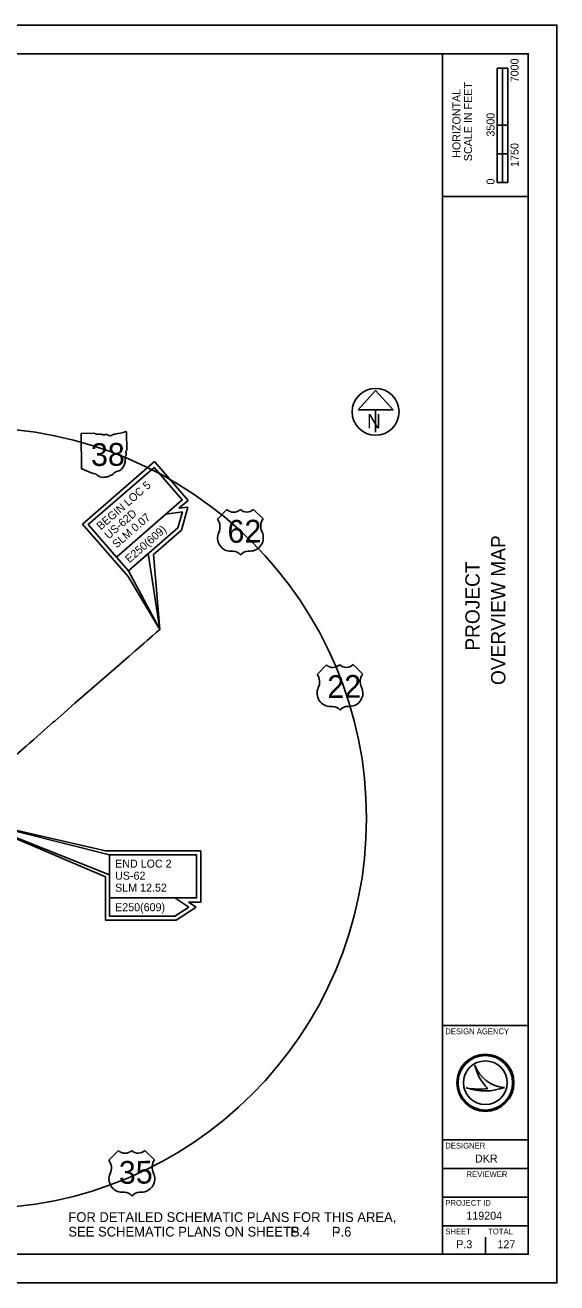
# Model space of a CAD drawing. Extents: x 86259 to 205259, y 423331 to 500331.
# Drawn here: x 172720 to 205259, y 423331 to 500331 of the extents above; entities that cross this region are included whole.
import ezdxf

# ---------------------------------------------------------------- set-up
doc = ezdxf.new("R2010")
doc.units = 0
for name, color, linetype in [('Default', 7, 'Continuous'), ('GM_X_County_Subdivision', 7, 'Continuous'), ('PM_P_Cells', 7, 'Continuous'), ('SC_Scratch1', 7, 'Continuous'), ('SH_Border', 7, 'Continuous'), ('SH_Cut_Line', 7, 'Continuous'), ('SH_Data', 7, 'Continuous'), ('SH_Text', 7, 'Continuous'), ('SN_P_Signs', 7, 'Continuous'), ('XS_P_Annotation', 7, 'Continuous')]:
    doc.layers.add(name, color=color, linetype=linetype)

msp = doc.modelspace()

# ---------------------------------------------------------------- linework, layer by layer
at = {"layer": 'GM_X_County_Subdivision'}
msp.add_circle((194167, 476659), 1435, dxfattribs=at)
at = {"layer": 'PM_P_Cells'}
for points in [[(180957, 463326), (180739, 463138), (180515, 462947), (180182, 462655), (180008, 462503), (179441, 462008), (179088, 461702), (177988, 460749), (177695, 460495), (177082, 459964), (176952, 459851), (175768, 458815), (175103, 458232), (174548, 457746), (174416, 457630)], [(174416, 457630), (173884, 457161), (173467, 456791), (173222, 456574), (172987, 456373), (172774, 456190), (172520, 455957), (172483, 455922), (172034, 455537), (171782, 455312), (171481, 455055)]]:
    msp.add_lwpolyline(points, dxfattribs=at)
at = {"layer": 'SC_Scratch1'}
for p, q in [((180630, 473610), (176228, 469788)), ((182689, 471239), (180630, 473610)), ((182130, 470754), (182689, 471239)), ((182682, 470828), (182130, 470754)), ((182284, 469414), (182682, 470828)), ((176228, 469788), (179016, 466577)), ((180570, 467926), (182284, 469414)), ((180957, 463326), (180570, 467926)), ((179016, 466577), (180957, 463326)), ((169524, 451634), (177634, 449784)), ((177634, 448192), (169524, 451634)), ((177634, 449784), (183464, 449784)), ((183464, 449784), (183464, 446644)), ((177634, 445531), (177634, 448192)), ((183464, 446644), (182724, 446644)), ((182724, 446644), (183190, 446338)), ((183190, 446338), (181962, 445531)), ((181962, 445531), (177634, 445531))]:
    msp.add_line(p, q, dxfattribs=at)
at = {"layer": 'SH_Border'}
for p, q in [((198259, 425081), (198259, 498581)), ((198259, 489831), (203509, 489831)), ((198259, 439081), (203509, 439081)), ((198259, 432081), (203509, 432081)), ((198259, 430331), (203509, 430331)), ((198259, 428581), (203509, 428581)), ((198259, 426831), (203509, 426831))]:
    msp.add_line(p, q, dxfattribs=at)
msp.add_lwpolyline([(91509, 498581), (203509, 498581), (203509, 425081), (91509, 425081)], close=True, dxfattribs=at)
msp.add_circle((169707, 451775), 23903, dxfattribs=at)
at = {"layer": 'SH_Cut_Line'}
msp.add_lwpolyline([(86259, 423331), (205259, 423331), (205259, 500331), (86259, 500331)], close=True, dxfattribs=at)
at = {"layer": 'SH_Data'}
for p, q in [((201607, 490706), (201607, 497706)), ((202263, 497706), (201607, 497706)), ((201607, 494206), (201607, 497706)), ((201607, 497706), (201934, 497706)), ((201934, 497706), (201937, 497706)), ((201937, 497706), (201937, 494206)), ((202263, 497706), (202263, 490706)), ((201937, 494206), (201607, 494206)), ((202260, 494206), (201934, 494206)), ((201934, 494206), (201934, 492456)), ((202260, 492456), (202260, 494206)), ((201934, 492456), (201607, 492456)), ((201607, 492456), (201607, 490706)), ((201934, 490706), (201934, 492456)), ((201934, 492456), (202260, 492456)), ((202263, 490706), (201607, 490706)), ((201607, 490706), (201934, 490706)), ((182339, 470530), (181334, 470394)), ((182339, 470530), (182064, 469554)), ((178311, 467770), (181334, 470394)), ((179040, 466930), (182064, 469554)), ((178311, 467770), (179040, 466930)), ((177884, 446894), (177884, 445781)), ((182735, 446338), (181888, 446894)), ((182735, 446338), (181888, 445781)), ((177884, 445781), (181888, 445781)), ((200245, 436665), (200245, 436665)), ((199719, 435265), (199719, 435265)), ((200884, 435581), (200884, 435581)), ((202064, 435296), (202064, 435296)), ((200884, 425081), (200884, 426131)), ((199571, 425694), (199571, 425694))]:
    msp.add_line(p, q, dxfattribs=at)
for points in [[(178311, 467770), (182336, 471264), (180605, 473258), (176580, 469763)], [(179040, 466930), (180957, 463326), (180257, 467986)], [(177884, 448308), (169524, 451634), (177884, 449534)], [(177884, 449534), (183214, 449534), (183214, 446894), (177884, 446894)]]:
    msp.add_lwpolyline(points, close=True, dxfattribs=at)
for radius in [1750, 1669, 1669, 1338]:
    msp.add_circle((200884, 435581), radius, dxfattribs=at)
for centre, radius, start, end in [((202164, 437323), 2029, 198.92567, 198.93195), ((202972, 437227), 2785, 191.63793, 191.64215), ((202164, 437323), 2029, 198.93195, 267.16574), ((202972, 437227), 2785, 191.64215, 226.09467), ((200847, 438626), 3546, 251.45764, 290.08324), ((200527, 439622), 4431, 259.49639, 259.49952), ((200847, 438626), 3546, 251.45274, 251.45764), ((200527, 439622), 4431, 259.49952, 276.66723)]:
    msp.add_arc(centre, radius, start, end, dxfattribs=at)
at = {"layer": 'SH_Text'}
for p, q in [((194167, 477968), (193090, 476773)), ((195243, 476773), (194167, 477968)), ((193090, 476773), (195243, 476773)), ((194167, 476773), (194167, 475420))]:
    msp.add_line(p, q, dxfattribs=at)
msp.add_circle((194167, 476659), 1435, dxfattribs=at)
at = {"layer": 'SN_P_Signs'}
for p, q in [((185068, 470671), (184493, 470086)), ((187277, 470112), (186692, 470686)), ((185324, 468121), (185440, 468122)), ((186368, 468131), (186484, 468132)), ((191160, 461166), (190585, 460580)), ((193369, 460607), (192784, 461181)), ((191416, 458616), (191532, 458617)), ((192460, 458626), (192576, 458627)), ((178422, 431424), (177847, 430838)), ((180632, 430865), (180046, 431439)), ((178678, 428874), (178794, 428875)), ((179722, 428884), (179838, 428885))]:
    msp.add_line(p, q, dxfattribs=at)
for centre, radius, start, end in [((185470, 471089), 580, 226.11154, 314.96555), ((186282, 471097), 580, 226.11154, 314.96555), ((183832, 469614), 812, 335.08567, 35.53948), ((187947, 469652), 812, 145.53762, 205.99142), ((185307, 468933), 812, 155.37047, 271.17681), ((186485, 468944), 812, 269.90028, 25.70663), ((185445, 467542), 580, 37.40844, 90.53855), ((186373, 467551), 580, 90.53855, 143.66865), ((189924, 460108), 812, 335.08567, 35.53948), ((191562, 461584), 580, 226.11154, 314.96555), ((192374, 461592), 580, 226.11154, 314.96555), ((194039, 460147), 812, 145.53762, 205.99142), ((191399, 459428), 812, 155.37047, 271.17681), ((192577, 459439), 812, 269.90028, 25.70663), ((191537, 458037), 580, 37.40844, 90.53855), ((192465, 458046), 580, 90.53855, 143.66865), ((178824, 431842), 580, 226.11154, 314.96555), ((179636, 431850), 580, 226.11154, 314.96555), ((177187, 430366), 812, 335.08567, 35.53948), ((181301, 430405), 812, 145.53762, 205.99142), ((178661, 429686), 812, 155.37047, 271.17681), ((179840, 429697), 812, 269.90028, 25.70663), ((178799, 428295), 580, 37.40844, 90.53855), ((179728, 428304), 580, 90.53855, 143.66865)]:
    msp.add_arc(centre, radius, start, end, dxfattribs=at)
at = {"layer": 'XS_P_Annotation'}
for p, q in [((176138, 475299), (176158, 473186)), ((176980, 475344), (176165, 475336)), ((178932, 474309), (178921, 475414)), ((178932, 474309), (178932, 474309))]:
    msp.add_line(p, q, dxfattribs=at)
for centre, radius, start, end in [((176170, 475304), 32.3, 98.66865, 188.66865), ((177172, 475591), 313, 232.15805, 271.65043), ((177290, 474160), 1123, 81.02524, 95.52682), ((177534, 475328), 90.3, 220.33061, 297.64092), ((177668, 475085), 188, 55.00523, 119.67968), ((177907, 475422), 226, 234.39475, 295.36674), ((178313, 474711), 594, 97.88473, 121.3074), ((177903, 478234), 2953, 276.38302, 289.445), ((178890, 475419), 31, 352.40063, 98.27655), ((178111, 473698), 739, 292.84743, 9.52439), ((179047, 473847), 210, 137.34504, 187.46814), ((178925, 474228), 48, 108.48253, 210.87551), ((178622, 474085), 288, 340.57151, 24.18811), ((178899, 474304), 33.2, 290.14236, 8.27268), ((176190, 473182), 32.5, 172.49693, 258.84516), ((176193, 473398), 248, 267.87754, 281.1424), ((176247, 473065), 89.5, 30.28693, 93.81029), ((177360, 474974), 2132, 240.95147, 257.73705), ((176750, 472242), 667, 47.7227, 76.37452), ((177917, 472998), 239, 283.41174, 323.81566), ((178433, 472614), 404, 94.94167, 143.1153), ((177463, 473066), 423, 231.23892, 286.83038), ((177715, 472338), 348, 86.23367, 111.74849), ((177740, 472910), 226, 269.31557, 316.08782), ((177946, 472708), 63.5, 66.29028, 133.18697)]:
    msp.add_arc(centre, radius, start, end, dxfattribs=at)

# ---------------------------------------------------------------- texts
at = {"layer": 'Default'}
for s, p in [('BEGIN LOC 5', (177349, 469394)), ('US-62D', (177831, 468839)), ('SLM 0.07', (178313, 468284)), ('E250(609)', (179098, 467379))]:
    msp.add_text(s, height=490, rotation=40.96278, dxfattribs=at).set_placement(p)
for s, p in [('END LOC 2', (178223, 448751)), ('US-62', (178223, 448016)), ('SLM 12.52', (178223, 447281)), ('E250(609)', (178223, 446083))]:
    msp.add_text(s, height=490, dxfattribs=at).set_placement(p)
at = {"layer": 'SH_Data'}
for s, height, p in [('7000', 490, (202915, 496834)), ('SCALE IN FEET', 490, (200070, 492003)), ('HORIZONTAL', 490, (199361, 492209)), ('3500', 490, (201445, 493509)), ('1750', 490, (202915, 491655)), ('0', 490, (201445, 490571)), ('OVERVIEW MAP', 875, (202109, 459932)), ('PROJECT', 875, (200534, 462036))]:
    msp.add_text(s, height=height, rotation=90, dxfattribs=at).set_placement(p)
for s, height, p in [('DESIGN AGENCY', 350, (198434, 438556)), ('DESIGNER', 350, (198434, 431556)), ('DKR', 490, (200251, 430699)), ('REVIEWER', 350, (199735, 429806)), ('PROJECT ID', 350, (198434, 428056)), ('FOR DETAILED SCHEMATIC PLANS FOR THIS AREA,', 595, (175365, 427058)), ('119204', 490, (199721, 427199)), ('SEE SCHEMATIC PLANS ON SHEETS          -', 595, (175365, 426166)), ('P.4', 595, (188954, 426166)), ('P.6', 595, (191491, 426166)), ('SHEET', 350, (198434, 426306)), ('TOTAL', 350, (201059, 426306)), ('P.3', 490, (199102, 425449)), ('127', 490, (201627, 425449))]:
    msp.add_text(s, height=height, dxfattribs=at).set_placement(p)
at = {"layer": 'SH_Text'}
msp.add_text('N', height=875, dxfattribs=at).set_placement((193637, 475640))
at = {"layer": 'SN_P_Signs'}
for s, p in [('62', (185111, 468641)), ('22', (191220, 459136)), ('35', (178461, 429394))]:
    msp.add_text(s, height=1392.2, rotation=0.53855, dxfattribs=at).set_placement(p)
at = {"layer": 'XS_P_Annotation'}
msp.add_text('38', height=1392.2, rotation=0.53855, dxfattribs=at).set_placement((176753, 473341))

doc.saveas('drawing.dxf')
